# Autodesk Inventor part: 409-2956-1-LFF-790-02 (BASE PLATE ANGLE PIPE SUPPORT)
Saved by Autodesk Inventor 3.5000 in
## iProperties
Created: 2010-09
Part Number: 409-2956-1-LFF-790-02 (BASE PLATE ANGLE PIPE SUPPORT)
Cost Center: 0 lbmass
Material: A304 STAINLESS STEEL
Document SubType Name: Sheet Metal
Designer: S. Boerckel
Authority: 0 in^3
Mass: 1027.78 g
Surface Area: 319.706 cm^2
Volume: 127.201 cm^3
Density: 8.08 g/cm^3
Flat Pattern Width: 8.89 cm
Flat Pattern Length: 15.24 cm
Flat Pattern Area: 135.484 cm^2
Sheet Metal Rule: 3/8"Thk
Sheet Metal Width: 6.0000 in
Sheet Metal Length: 21.0000 in^2
Description: BASE PLATE
User Status: BURN
SaveDate: 2008-01-15
SaveTime: 10:24
FileName: Sheet Metal
Wide: =<Flat Pattern Width>cm
Length: =<Flat Pattern Length>cm
Thickness: 0.3750 in
SMR: =<Sheet Metal Rule> - <Material>
Author: S. Boerckel
Revision Number: 0
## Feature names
1. Hole1
2. Plate1
